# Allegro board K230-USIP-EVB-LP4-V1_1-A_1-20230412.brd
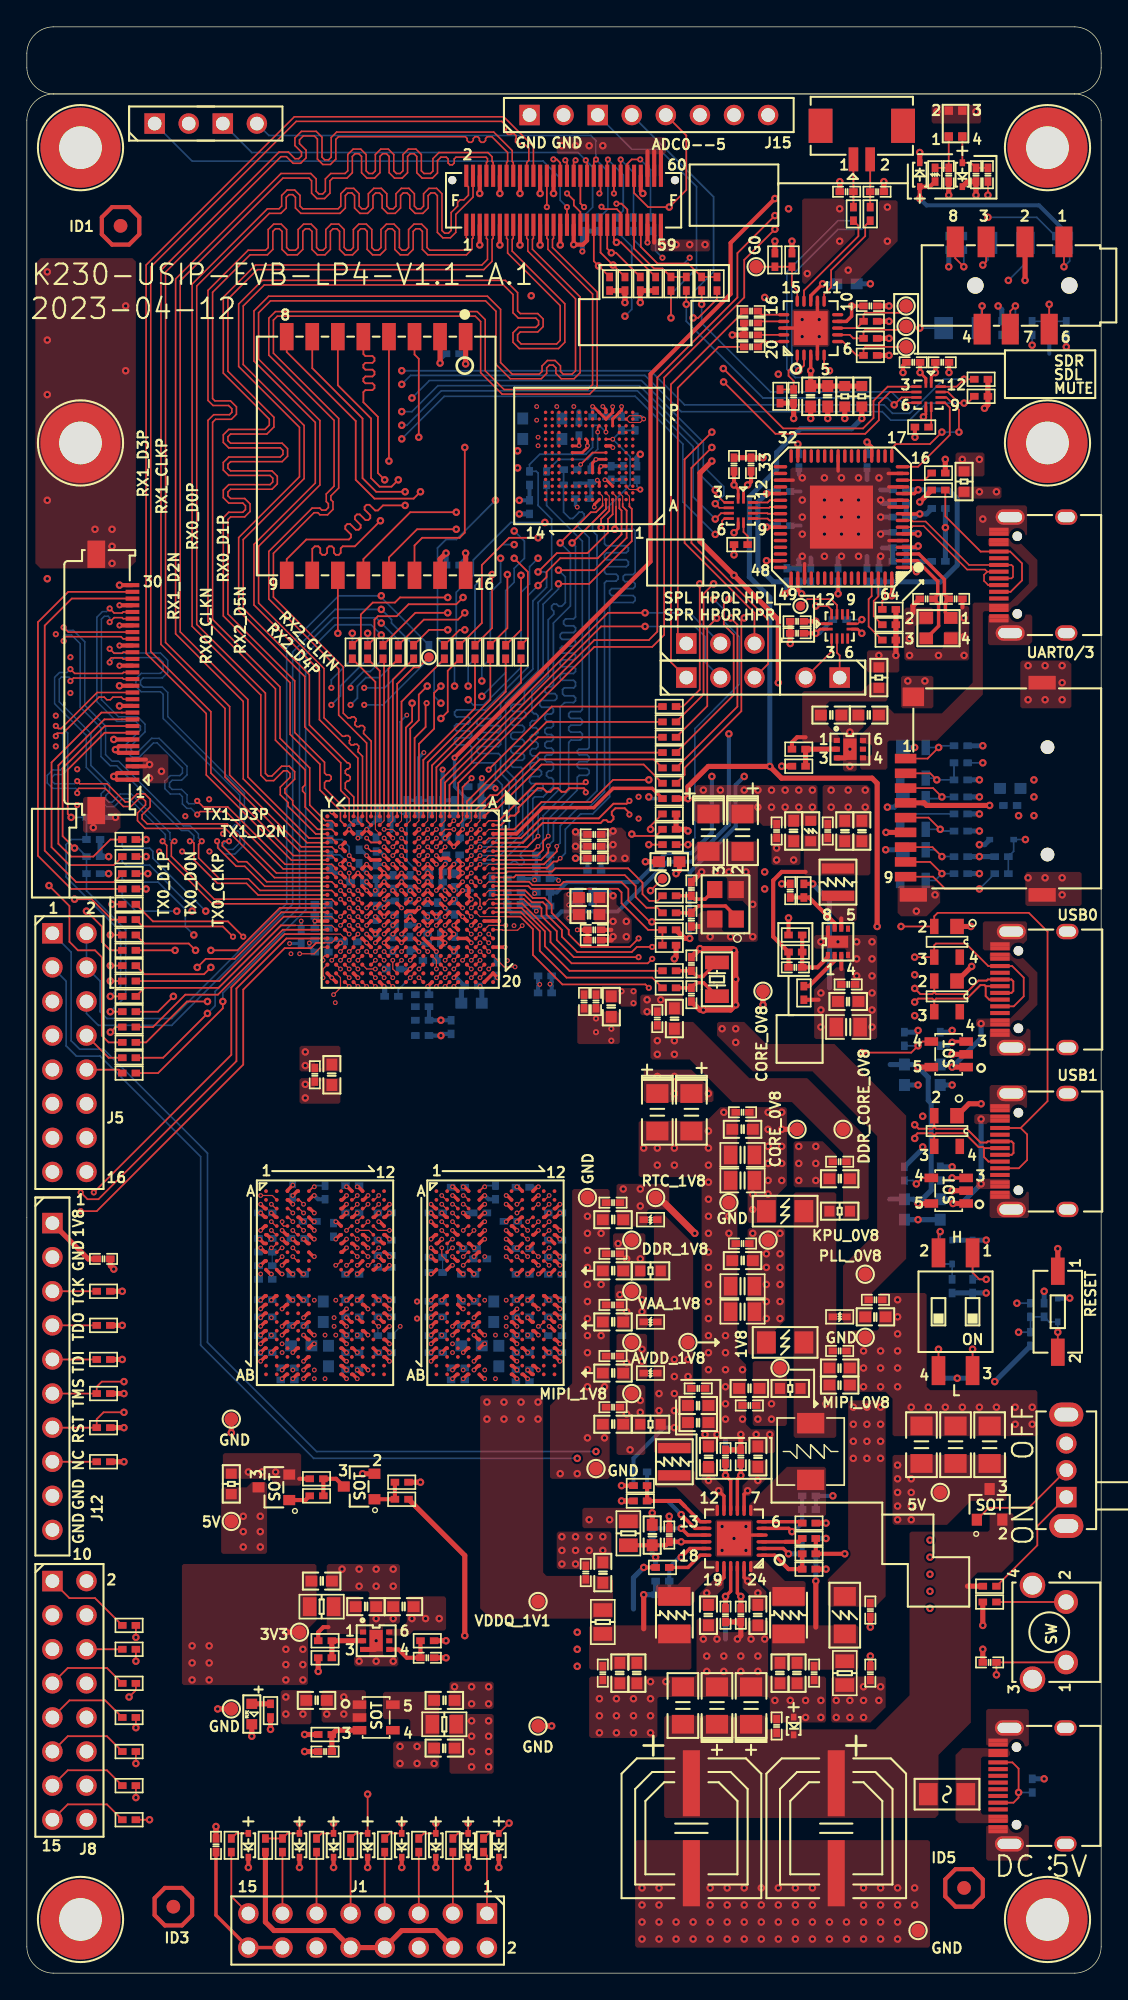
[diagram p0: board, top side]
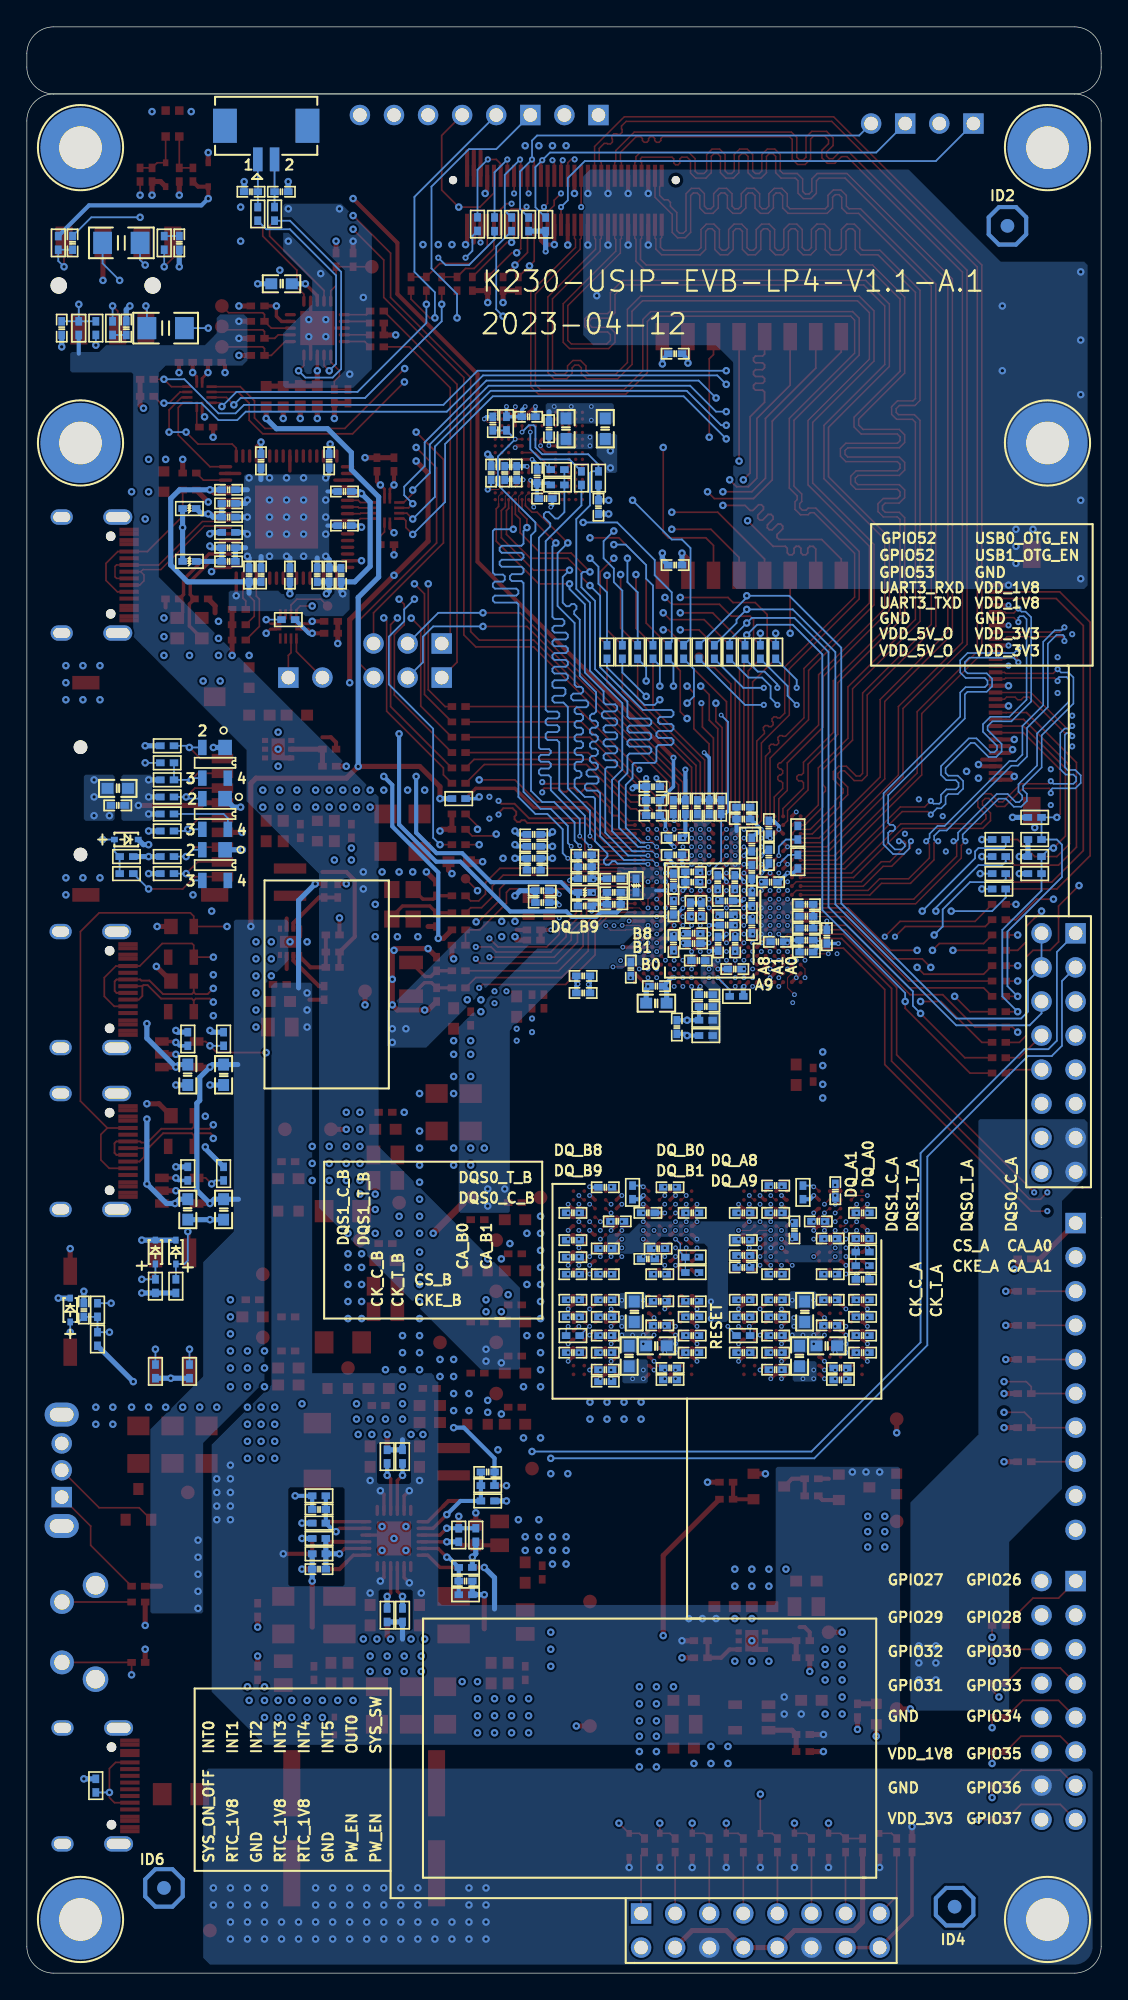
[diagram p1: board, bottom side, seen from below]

Outline 80.07 x 145 mm; copper layers: TOP, GND02, ART03, POWER04, GND05, ART06, GND07, BOTTOM. Coordinates in mm from the lower left corner of the outline.
Outline path: 2,140 arc(0.59,139.41) 0,138 0,2 arc(0.59,0.59) 2,0 78.07,0 arc(79.48,0.59) 80.07,2 80.07,138 arc(79.48,139.41) 78.07,140 ; 2,140 arc(0.59,140.59) 0,142 0,143 arc(0.59,144.41) 2,145 78.07,145 arc(79.48,144.41) 80.07,143 80.07,142 arc(79.48,140.59) 78.07,140 ; 2,140 78.07,140 ; 2,140 78.07,140

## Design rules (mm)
net group 3D_CTRL_IN: nets 3D_CTRL_IN N21013370
net group 3D_CTRL_OUT1: nets 3D_CTRL_OUT1 N21013374
net group 3D_CTRL_OUT2: nets 3D_CTRL_OUT2 N21013378
net group ADC_2: nets ADC_2 N21252475
net group ADC_3: nets ADC_3 N21252478
net group ADC_4: nets ADC_4 N21252481
net group DIFF100: nets DEBUG_DM DEBUG_DP
net group DL_M_CLK2: nets DL_M_CLK2 N21014154
net group DL_M_CLK3: nets DL_M_CLK3 N21014156
net group DP_M_CLK1: nets DP_M_CLK1 N21013382
net group EMMC_CLK: nets EMMC_CLK N21433380
net group EMMC_STROBE: nets EMMC_STROBE N21377535
net group GPIO26: nets GPIO26 N21015638
net group GPIO27: nets GPIO27 N21015640
net group GPIO28: nets GPIO28 N21015650
net group GPIO32: nets GPIO32 N21015658
net group GPIO33: nets GPIO33 N21015660
net group GPIO34: nets GPIO34 N21015662
net group GPIO35: nets GPIO35 N21015664
net group GPIO36: nets GPIO36 N21015666
net group GPIO37: nets GPIO37 N21015668
net group GPIO47: nets GPIO47 N21014397
net group GPIO48: nets GPIO48 N21014399
net group GPIO49: nets GPIO49 N21014401
net group GPIO52: nets GPIO52 N21015121
net group GPIO60_3V3: nets GPIO60_3V3 N21015137
net group GPIO61_3V3: nets GPIO61_3V3 N21015139
net group I2C1_SCL: nets I2C1_SCL N21014383
net group I2C1_SDA: nets I2C1_SDA N21014385
net group I2C3_SCL: nets I2C3_SCL N21014391
net group I2C3_SDA: nets I2C3_SDA N21014393
net group I2C4_SCL: nets I2C4_SCL N21013358
net group I2C4_SDA: nets I2C4_SDA N21013362
net group MMC1_CLK: nets MMC1_CLK N21015127
net group MMC1_CMD: nets MMC1_CMD N21015125
net group MMC1_D0: nets MMC1_D0 N21015129
net group MMC1_D1: nets MMC1_D1 N21015131
net group MMC1_D2: nets MMC1_D2 N21015133
net group MMC1_D3: nets MMC1_D3 N21015135
net group N21049039: nets N21049039 N21049045
net group N21049041: nets N21049041 N21049043
net group RESET_N_A_B: nets N21620702 RESET_N_A_B
net group RTC_CLK_IN: nets N20962782 RTC_CLK_IN
net group RTC_CLK_OUT: nets N20962780 RTC_CLK_OUT
net group RTC_INT0: nets N21140162 RTC_INT0
net group RTC_INT1: nets N21140164 RTC_INT1
net group RTC_INT2: nets N21140180 RTC_INT2
net group RTC_INT3: nets N21140182 RTC_INT3
net group RTC_INT4: nets N21259420 RTC_INT4
net group RTC_INT5: nets N21259407 RTC_INT5
net group RTC_OUT0: nets N21259441 RTC_OUT0
net group RTC_OUT1: nets RTC_OUT1 SYS_RST
net group SYS_CLK_IN: nets N20990724 SYS_CLK_IN
net group SYS_CLK_OUT: nets N20990759 SYS_CLK_OUT
net group SYS_SW: nets N21259446 SYS_SW
net group UART3_RXD: nets N21015111 UART3_RXD
net group UART3_TXD: nets N21015109 UART3_TXD
net group 18MIL: nets EMMC_RST JTAG_RST JTAG_TCK
net group ADC_0: nets ADC_0 HSY0 N21014379 N21252465 UART0_TXD
net group ADC_1: nets ADC_1 N21014381 N21252472 UART0_RXD VSY0
net group ADC_5: nets ADC_5 HP_INSERT_DET N21252484
net group BUS-DATA1-A: nets DQ_A13
net group DIFF90: nets USB0_DN USB0_DP USB1_DN USB1_DP
net group DP_RST: nets DP_RST GPIO46 N21014395
net group DP_STROBE: nets DP_STROBE GPIO42 N21014387
net group DP_VSYNC: nets DP_VSYNC GPIO43 N21014389
net group GPIO9: nets GPIO9 LCD_RST N21013366
net group GPIO29: nets GPIO29 N21015652 TOUCH_INT
net group GPIO30: nets GPIO30 N21015654 TOUCH_RST
net group GPIO31: nets GPIO31 LCD_EN N21015656
net group GPIO53: nets GPIO53 N21015123 N21453086

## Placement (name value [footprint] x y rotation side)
C1  100nF/16V  [C0402]  71.75 23.15 180 top
C2  22uF/16V-1206  [C1206]  71.75 39.37 90 top
C3  12pF/50V  [C0402]  49.53 72.9 270 top
C4  12pF/50V  [C0402]  49.53 75.18 90 top
C5  100nF/16V  [C0402]  31.88 76.71 270 bottom
C6  100nF/16V  [C0402]  35.05 74.8 270 bottom
C7  10uF/10V-0603  [C0603]  58.42 117.47 270 top
C8  12pF/50V  [C0402]  49.53 78.49 270 top
C9  22uF/16V-1206  [C1206]  48.9 19.94 90 top
C10  1nF/50V  [C0402]  63.36 132.72 0 bottom
C11  12pF/50V  [C0402]  49.53 80.77 90 top
C12  100nF/16V  [C0402]  55.88 18.41 90 top
C13  100nF/16V  [C0402]  75.82 49.4 270 bottom
C14  100nF/16V  [C0402]  31.75 83.31 180 bottom
C15  100nF/16V  [C0402]  42.29 83.06 0 bottom
C16  10uF/10V-0603  [C0603]  65.41 66.93 90 bottom
C17  10uF/10V-0603  [C0603]  68.07 66.93 270 bottom
C18  100nF/16V  [C0402]  41.15 115.06 90 bottom
C19  1uF/6.3V  [C0402]  44.45 111.76 270 bottom
C20  10uF/10V-0603  [C0603]  65.41 56.9 90 bottom
C21  10uF/10V-0603  [C0603]  68.07 56.9 270 bottom
C22  100nF/16V  [C0402]  43.56 111.76 270 bottom
C23  10uF/10V-0603  [C0603]  36.96 115.06 270 bottom
C24  100nF/16V  [C0402]  45.47 111.76 90 bottom
C25  100nF/16V  [C0402]  45.34 115.44 90 bottom
C26  100nF/16V  [C0402]  24.13 76.83 180 bottom
C27  100nF/16V  [C0402]  28.32 86.87 90 bottom
C28  100nF/16V  [C0402]  21.97 79.63 180 bottom
C29  100nF/16V  [C0402]  30.1 86.87 90 bottom
C30  100nF/16V  [C0402]  26.67 85.98 180 bottom
C31  100nF/16V  [C0402]  21.97 77.85 180 bottom
C32  100nF/16V  [C0402]  31.88 79.38 90 bottom
C33  10uF/10V-0603  [C0603]  41.91 80.14 0 top
C34  1uF/6.3V  [C0402]  42.29 76.96 0 top
C35  100nF/16V  [C0402]  38.48 81.53 180 bottom
C36  100nF/16V  [C0402]  38.61 73.03 0 bottom
C37  100nF/16V  [C0402]  38.61 74.3 0 bottom
C38  100nF/16V  [C0402]  28.57 81.28 270 bottom
C39  100nF/16V  [C0402]  27.3 81.28 270 bottom
C40  100nF/16V  [C0402]  27.94 79.88 180 bottom
C41  10uF/10V-0603  [C0603]  41.91 78.87 0 top
C42  1uF/6.3V  [C0402]  42.29 77.72 0 top
C43  100nF/16V  [C0402]  41.66 80.64 0 bottom
C44  100nF/16V  [C0402]  41.66 79.76 0 bottom
C45  100nF/16V  [C0402]  38.48 83.31 180 bottom
C46  100nF/16V  [C0402]  26.04 77.98 270 bottom
C47  100nF/16V  [C0402]  26.04 80.01 90 bottom
C48  100nF/16V  [C0402]  38.48 82.42 180 bottom
C49  10uF/10V-0603  [C0603]  47.88 82.8 0 top
C50  1uF/6.3V  [C0402]  42.29 83.95 0 top
C51  100nF/16V  [C0402]  42.29 84.84 0 top
C52  100nF/16V  [C0402]  30.48 81.28 0 bottom
C53  100nF/16V  [C0402]  42.29 83.95 0 bottom
C54  100nF/16V  [C0402]  42.29 84.84 0 bottom
C55  100nF/16V  [C0402]  42.29 83.06 0 top
C56  100nF/16V  [C0402]  30.48 82.04 0 bottom
C57  10uF/10V-0603  [C0603]  43.56 72.01 270 top
C58  1uF/6.3V  [C0402]  30.61 79.25 90 bottom
C59  100nF/16V  [C0402]  42.42 72.39 270 top
C60  100nF/16V  [C0402]  41.53 72.39 270 top
C61  100nF/16V  [C0402]  29.79 79.25 90 bottom
C62  100nF/16V  [C0402]  29.46 72.01 0 bottom
C63  10uF/10V-0603  [C0603]  48.26 71.12 90 top
C64  1uF/6.3V  [C0402]  46.99 71.12 90 top
C65  100nF/16V  [C0402]  21.97 76.96 0 bottom
C66  100nF/16V  [C0402]  21.97 76.07 0 bottom
C67  100nF/16V  [C0402]  27.91 78.84 180 bottom
C68  100nF/16V  [C0402]  27.91 78.08 0 bottom
C69  10uF/10V-0603  [C0603]  22.73 66.93 270 top
C70  1uF/6.3V  [C0402]  21.46 66.93 270 top
C71  100nF/16V  [C0402]  27.3 74.8 0 bottom
C72  100nF/16V  [C0402]  31.62 70.48 270 bottom
C73  100nF/16V  [C0402]  30.38 77.47 0 bottom
C74  100nF/16V  [C0402]  28.55 76.68 270 bottom
C75  100nF/16V  [C0402]  27.28 76.68 270 bottom
C76  1uF/6.3V  [C0402]  33.15 73.53 180 bottom
C77  100nF/16V  [C0402]  30.38 76.71 0 bottom
C78  1uF/6.3V  [C0402]  38.48 79.5 180 bottom
C79  100nF/16V  [C0402]  29.21 86.87 90 bottom
C80  100nF/16V  [C0402]  21.97 78.74 180 bottom
C81  1uF/6.3V  [C0402]  26.67 86.87 180 bottom
C82  100nF/16V  [C0402]  36.32 80.52 0 bottom
C83  1uF/6.3V  [C0402]  36.32 79.63 0 bottom
C84  100nF/16V  [C0402]  36.32 81.53 0 bottom
C85  1uF/6.3V  [C0402]  24.77 85.34 90 bottom
C86  100nF/16V  [C0402]  24.77 83.19 90 bottom
C87  100nF/16V  [C0402]  26.04 84.07 90 bottom
C88  1uF/6.3V  [C0402]  20.45 77.22 90 bottom
C89  100nF/16V  [C0402]  24.64 81.28 180 bottom
C90  100nF/16V  [C0402]  26.04 82.04 270 bottom
C91  10uF/10V-0603  [C0603]  22.48 45.97 270 bottom
C92  1uF/6.3V  [C0402]  26.67 50.16 180 bottom
C93  100nF/16V  [C0402]  24.26 56.64 0 bottom
C94  100nF/16V  [C0402]  26.67 46.23 180 bottom
C95  100nF/16V  [C0402]  26.67 56.64 180 bottom
C96  100nF/16V  [C0402]  26.67 53.47 180 bottom
C97  100nF/16V  [C0402]  19.81 58.29 90 bottom
C98  100nF/16V  [C0402]  24.26 47.5 0 bottom
C99  100nF/16V  [C0402]  24.26 50.16 180 bottom
C100  100nF/16V  [C0402]  24.26 52.07 180 bottom
C101  100nF/16V  [C0402]  21.08 56.01 180 bottom
C102  100nF/16V  [C0402]  26.67 52.58 180 bottom
C103  10uF/10V-0603  [C0603]  20.45 46.74 180 bottom
C104  1uF/6.3V  [C0402]  26.67 48.9 180 bottom
C105  100nF/16V  [C0402]  22.86 55.37 90 bottom
C106  100nF/16V  [C0402]  17.78 48.9 0 bottom
C107  100nF/16V  [C0402]  20.19 52.07 0 bottom
C108  100nF/16V  [C0402]  17.78 56.64 0 bottom
C109  100nF/16V  [C0402]  17.78 50.16 0 bottom
C110  100nF/16V  [C0402]  20.19 50.16 0 bottom
C111  100nF/16V  [C0402]  17.78 46.23 0 bottom
C112  100nF/16V  [C0402]  19.43 44.2 180 bottom
C113  100nF/16V  [C0402]  19.43 45.09 0 bottom
C114  100nF/16V  [C0402]  24.26 44.96 0 bottom
C115  10uF/10V-0603  [C0603]  22.1 49.28 90 bottom
C116  1uF/6.3V  [C0402]  17.78 47.5 0 bottom
C117  100nF/16V  [C0402]  26.67 54.61 180 bottom
C118  100nF/16V  [C0402]  20.19 54.74 0 bottom
C119  100nF/16V  [C0402]  17.78 54.74 180 bottom
C120  100nF/16V  [C0402]  24.26 48.9 0 bottom
C121  100nF/16V  [C0402]  20.19 48.26 0 bottom
C122  100nF/16V  [C0402]  24.26 46.23 0 bottom
C123  100nF/16V  [C0402]  24.26 58.67 0 bottom
C127  2.2uF/10V-0603  [C0603]  28.07 27.3 180 top
C128  22uF/6.3V-0603  [C0603]  25.27 27.3 180 top
C129  NC  [C0402]  29.84 23.5 0 top
C139  100nF/16V  [C0402]  73.29 87 0 bottom
C145  22uF/6.3V-0603  [C0603]  73.29 88.27 0 bottom
C149  4.7uF/6.3V  [C0402]  30.99 86.87 90 bottom
C150  100nF/16V  [C0402]  31.75 84.58 0 bottom
C151  4.7uF/6.3V  [C0402]  42.29 82.17 0 bottom
C152  4.7uF/6.3V  [C0402]  33.4 86.23 0 bottom
C153  100nF/16V  [C0402]  33.4 87.38 0 bottom
C154  100nF/16V  [C0402]  33.4 88.39 0 bottom
C155  100nF/16V  [C0402]  68.71 133.99 270 top
C156  100nF/16V  [C0402]  31.88 86.87 90 bottom
C157  100nF/16V  [C0402]  76.66 128.91 270 bottom
C158  100nF/16V  [C0402]  68.71 128.91 90 bottom
C159  22uF/16V-1206  [C1206]  69.72 122.56 0 bottom
C160  100nF/16V  [C0402]  72.66 122.56 270 bottom
C161  22uF/16V-1206  [C1206]  73.03 128.91 180 bottom
C162  100nF/16V  [C0402]  77.47 122.56 270 bottom
C199  4.7uF/6.3V  [C0402]  65.03 110.51 0 bottom
C200  100nF/16V  [C0402]  57.54 112.67 90 bottom
C201  12pF/50V  [C0402]  67.06 102.38 180 top
C202  100nF/16V  [C0402]  56.65 104.16 270 bottom
C203  4.7uF/6.3V  [C0402]  62.62 112.67 90 bottom
C204  12pF/50V  [C0402]  69.22 102.38 0 top
C205  100nF/16V  [C0402]  31.88 81.41 90 bottom
C206  100nF/16V  [C0402]  5.71 53.21 180 top
C207  100nF/16V  [C0402]  66.06 120.01 180 top
C208  100nF/16V  [C0402]  68.22 120.01 180 top
C216  100nF/16V  [C0402]  58.43 104.16 270 bottom
C217  100nF/16V  [C0402]  57.54 104.16 270 bottom
C218  100nF/16V  [C0402]  60.46 104.16 270 bottom
C219  100nF/16V  [C0402]  56.4 107.84 180 bottom
C220  100nF/16V  [C0402]  62.61 104.16 270 bottom
C221  100nF/16V  [C0402]  56.4 110.38 180 bottom
C222  100nF/16V  [C0402]  63.51 104.16 270 bottom
C223  4.7uF/6.3V  [C0402]  65.03 108.48 180 bottom
C224  100nF/16V  [C0402]  65.03 109.49 180 bottom
C225  4.7uF/6.3V  [C0402]  65.03 106.19 180 bottom
C226  100nF/16V  [C0402]  65.03 105.18 180 bottom
C227  22uF/6.3V-0603  [C0603]  21.97 29.21 180 top
C238  100nF/16V  [C0402]  71.63 133.99 90 top
C242  100nF/16V  [C0402]  31.75 120.65 0 bottom
C244  10uF/10V-0603  [C0603]  39.88 115.06 270 bottom
C247  330uF/25V  [C1010_8383_6666]  49.53 10.79 180 top
C248  330uF/25V  [C1010_8383_6666]  60.33 10.79 180 top
C249  10uF/16V-1206  [TC1206]  51.44 19.94 90 top
C250  10uF/16V-1206  [TC1206]  53.98 19.94 90 top
C251  10uF/16V-1206  [TC1206]  49.53 64.14 270 top
C252  10uF/16V-1206  [TC1206]  53.34 84.96 270 top
C253  10uF/16V-1206  [TC1206]  46.99 64.14 270 top
C254  10uF/16V-1206  [TC1206]  50.8 84.96 270 top
C256  1uF/6.3V  [C0402]  41.4 109.86 180 bottom
C257  100nF/16V  [C0402]  42.67 115.95 180 bottom
C258  100nF/16V  [C0402]  42.04 111.51 90 bottom
C259  100nF/16V  [C0402]  37.47 109.22 270 bottom
C260  100nF/16V  [C0402]  31.75 104.9 180 bottom
C261  100nF/16V  [C0402]  29.46 72.9 180 bottom
C262  1nF/50V  [C0402]  30.02 75.44 0 bottom
C263  100nF/16V  [C0402]  17.78 51.69 180 bottom
C264  10uF/10V-0603  [C0603]  35.18 45.97 270 bottom
C265  1uF/6.3V  [C0402]  30.48 56.64 0 bottom
C266  100nF/16V  [C0402]  39.37 56.64 180 bottom
C268  NC  [C0402]  14.1 9.53 90 top
C269  10uF/10V-0603  [C0603]  33.15 72.26 180 bottom
C272  100nF/16V  [C0402]  32.13 58.55 180 bottom
C273  100nF/16V  [C0402]  36.96 50.16 180 bottom
C274  100nF/16V  [C0402]  39.37 46.23 180 bottom
C275  100nF/16V  [C0402]  30.48 46.23 0 bottom
C276  100nF/16V  [C0402]  36.96 52.07 180 bottom
C277  100nF/16V  [C0402]  36.96 47.5 0 bottom
C278  10uF/10V-0603  [C0603]  33.15 46.74 180 bottom
C279  1uF/6.3V  [C0402]  36.96 44.07 180 bottom
C280  100nF/16V  [C0402]  39.37 50.16 180 bottom
C281  100nF/16V  [C0402]  30.48 50.05 0 bottom
C282  100nF/16V  [C0402]  39.37 48.9 180 bottom
C283  100nF/16V  [C0402]  36.96 46.23 0 bottom
C284  100nF/16V  [C0402]  39.37 53.34 180 bottom
C285  100nF/16V  [C0402]  39.37 52.07 0 bottom
C286  100nF/16V  [C0402]  36.96 58.55 0 bottom
C287  100nF/16V  [C0402]  30.48 48.9 0 bottom
C288  100nF/16V  [C0402]  32.89 50.05 0 bottom
C289  100nF/16V  [C0402]  36.96 44.96 0 bottom
C290  100nF/16V  [C0402]  32.13 44.2 180 bottom
C291  100nF/16V  [C0402]  32.13 45.09 0 bottom
C292  100nF/16V  [C0402]  36.07 56.01 0 bottom
C293  100nF/16V  [C0402]  33.78 56.64 180 bottom
C294  100nF/16V  [C0402]  32.89 52.07 0 bottom
C295  100nF/16V  [C0402]  33.78 53.21 0 bottom
C296  10uF/10V-0603  [C0603]  34.8 49.28 90 bottom
C297  1uF/6.3V  [C0402]  36.96 48.9 0 bottom
C298  100nF/16V  [C0402]  39.37 54.61 180 bottom
C299  100nF/16V  [C0402]  33.02 53.98 180 bottom
C300  100nF/16V  [C0402]  36.96 53.99 0 bottom
C301  100nF/16V  [C0402]  32.89 48.26 0 bottom
C302  100nF/16V  [C0402]  30.48 47.5 0 bottom
C303  10uF/10V-0603  [C0603]  59.69 117.47 270 top
C304  10uF/10V-0603  [C0603]  61.09 125.86 0 bottom
C305  1nF/50V  [C0402]  61.1 132.72 180 bottom
C306  1nF/50V  [C0402]  61.1 132.72 180 top
C307  1nF/50V  [C0402]  63.36 132.72 0 top
C308  100nF/16V  [C0402]  62.87 124.21 0 top
C309  100nF/16V  [C0402]  53.98 121.16 0 top
C310  100nF/16V  [C0402]  53.98 122.05 0 top
C311  100nF/16V  [C0402]  53.98 123.83 0 top
C312  100nF/16V  [C0402]  53.98 122.94 0 top
C313  1uF/6.3V  [C0402]  57.15 117.47 270 top
C314  27pF/50V  [C0402]  70.74 133.99 270 top
C315  100nF/16V  [C0402]  57.4 99.82 180 top
C316  100nF/16V  [C0402]  57.4 100.71 0 top
C317  22uF/6.3V-0603  [C0603]  60.58 43.81 0 top
C318  100nF/16V  [C0402]  60.58 46.35 0 top
C319  22uF/6.3V-0603  [C0603]  60.58 45.09 0 top
C320  22pF/50V  [C0402]  58.29 34.54 180 bottom
C321  22uF/6.3V-0603  [C0603]  50.04 41.02 0 top
C322  22uF/6.3V-0603  [C0603]  50.04 42.29 0 top
C323  22pF/50V  [C0402]  45.72 37.34 0 bottom
C324  100nF/16V  [C0402]  50.04 43.56 0 top
C325  22uF/6.3V-0603  [C0603]  45.47 22.35 270 top
C326  100nF/16V  [C0402]  42.93 22.35 270 top
C327  22uF/6.3V-0603  [C0603]  44.2 22.35 270 top
C328  22pF/50V  [C0402]  47.37 29.21 0 bottom
C329  22uF/6.3V-0603  [C0603]  57.4 22.35 270 top
C330  100nF/16V  [C0402]  58.67 22.35 270 top
C331  22uF/6.3V-0603  [C0603]  56.13 22.35 270 top
C332  22pF/50V  [C0402]  58.29 30.1 180 bottom
C333  100nF/16V  [C0402]  52.07 38.48 90 top
C334  NC  [C0402]  53.21 38.48 90 top
C335  100nF/16V  [C0402]  53.21 26.67 270 top
C336  100nF/16V  [C0402]  52.07 26.67 270 top
C337  2.2uF/16V-0603  [C0603]  54.48 38.48 90 top
C338  2.2uF/16V-0603  [C0603]  50.8 26.67 270 top
C339  2.2uF/16V-0603  [C0603]  50.8 38.48 90 top
C340  2.2uF/16V-0603  [C0603]  54.48 26.67 270 top
C341  10uF/10V-0603  [C0603]  43.69 52.32 180 top
C342  100nF/16V  [C0402]  43.69 53.59 180 top
C343  10uF/10V-0603  [C0603]  43.69 56.13 180 top
C344  100nF/16V  [C0402]  43.69 57.4 180 top
C345  10uF/10V-0603  [C0603]  43.69 40.89 180 top
C346  100nF/16V  [C0402]  43.69 42.16 180 top
C347  10uF/10V-0603  [C0603]  42.93 29.84 90 top
C348  100nF/16V  [C0402]  41.66 29.84 90 top
C349  100nF/16V  [C0402]  47.88 32.64 90 top
C350  10uF/10V-0603  [C0603]  46.61 32.64 90 top
C351  100nF/16V  [C0402]  53.34 64.14 180 top
C352  10uF/10V-0603  [C0603]  53.34 62.87 180 top
C353  100nF/16V  [C0402]  53.34 54.36 180 top
C354  10uF/10V-0603  [C0603]  53.34 53.09 180 top
C357  100nF/16V  [C0402]  53.85 42.29 180 top
C358  10uF/10V-0603  [C0603]  53.85 43.56 180 top
C359  100nF/16V  [C0402]  43.69 49.78 180 top
C360  10uF/10V-0603  [C0603]  43.69 48.51 180 top
C361  100nF/16V  [C0402]  43.69 45.97 180 top
C362  10uF/10V-0603  [C0603]  43.69 44.7 180 top
C365  100nF/16V  [C0402]  63.25 50.16 0 top
C366  10uF/10V-0603  [C0603]  63.25 48.9 0 top
C367  100nF/16V  [C0402]  52.7 112.39 270 top
C368  100nF/16V  [C0402]  53.98 112.39 90 top
C369  22uF/6.3V-0603  [C0603]  59.94 93.73 180 top
C370  2.2uF/10V-0603  [C0603]  62.74 93.73 180 top
C371  47uF/6.3V-0805  [C0805]  53.34 60.96 180 top
C372  47uF/6.3V-0805  [C0805]  53.34 59.05 180 top
C373  47uF/6.3V-0805  [C0805]  53.34 49.28 180 top
C374  47uF/6.3V-0805  [C0805]  53.34 51.18 180 top
C375  10uF/10V-0603  [C0603]  57.15 85.09 270 top
C376  100nF/16V  [C0402]  55.88 85.09 270 top
C377  100nF/16V  [C0402]  59.69 85.09 270 top
C378  22uF/6.3V-0603  [C0603]  60.96 85.09 90 top
C379  10uF/10V-0603  [C0603]  61.21 72.39 0 top
C380  22uF/6.3V-0603  [C0603]  62.23 85.09 90 top
C381  100nF/16V  [C0402]  61.21 73.66 180 top
C382  22pF/50V  [C0402]  57.28 74.93 180 top
C383  22uF/16V-0805  [C0805]  61.21 70.48 0 top
C394  NC  [C0402]  56.9 80.64 90 top
C395  10uF/10V-0603  [C0603]  60.58 59.18 180 top
C396  100nF/16V  [C0402]  60.58 60.45 180 top
C397  22uF/16V-1206  [C1206]  66.67 39.37 90 top
C398  22uF/16V-1206  [C1206]  69.22 39.37 90 top
C399  100nF/16V  [C0402]  62.87 22.35 90 top
C400  100nF/16V  [C0402]  62.87 27.05 270 top
C401  2.2uF/10V-0603  [C0603]  21.59 20.32 180 top
C402  NC  [C0402]  22.23 16.51 180 top
C403  22uF/6.3V-0603  [C0603]  31.11 16.76 0 top
C404  22uF/6.3V-0603  [C0603]  31.11 20.32 180 top
D1  NC  [SOD523-2-28-H]  57.15 18.41 270 top
F1  3A-12V  [F1206]  68.58 13.34 180 top
FB1  600R/100MHz-500mA  [FB0402]  67.69 133.99 90 top
FB4  600R/100MHz-500mA  [FB0402]  34.67 81.03 270 bottom
FB5  600R/100MHz-500mA  [FB0402]  38.48 80.52 0 bottom
FB7  600R/100MHz-500mA  [FB0402]  67.95 105.18 180 bottom
FB8  600R/100MHz-500mA  [FB0402]  67.95 109.11 180 bottom
FB19  600R/100MHz-500mA  [FB0402]  46.48 56.13 180 top
FB26  600R/100MHz-500mA  [FB0402]  46.48 48.51 180 top
FB27  600R/100MHz-500mA  [FB0402]  46.48 44.7 180 top
FB29  600R/100MHz-500mA  [FB0402]  60.58 48.9 0 top
FB31  30R/4A  [FB1206]  56.52 56.77 180 top
FB32  30R/4A  [FB1206]  56.52 46.99 180 top
FB34  NC  [FB0603]  58.42 85.09 90 top
FB38  NC  [FB1206]  60.96 26.67 90 top
GPIO1  TEST POINT SMD circle 35 mils  [TP28]  57.66 101.85 0 top
GPIO25  TEST POINT SMD circle 35 mils  [TP28]  29.97 98.04 0 top
ID1  -  [unnamed]  6.99 130.18 0 top
ID2  -  [unnamed]  6.99 130.18 180 bottom
ID3  -  [unnamed]  10.92 4.95 0 top
ID4  -  [unnamed]  10.92 4.95 180 bottom
ID5  -  [unnamed]  69.85 6.35 0 top
ID6  -  [unnamed]  69.85 6.35 180 bottom
J1  2X8_2.54mm  [HEAD2X8-100]  34.29 4.45 180 top
J2  TYPE-C  [TYPE-C-USB16-20-126-H-SMD-B]  76.36 13.95 90 top
J3  TH243-G60S-W0R01  [BTB2X30-050-F-SMD]  40.01 132.08 0 top
J4  FPC-05F-30PH20  [FPC30-005-0520-75]  7.87 96.16 270 top
J5  2X8_2.54mm  [HEAD2X8-100]  1.91 77.47 270 top
J6  TYPE-C  [TYPE-C-USB16-20-126-H-SMD-B]  76.42 104.16 90 top
J7  PJ35367  [AUDIO-PJ3536-7-197]  74.3 125.73 270 top
J8  2X8_2.54mm  [HEAD2X8-100]  1.91 29.21 270 top
J9  Flash-EXT  [SOP16-75]  26.04 113.03 270 top
J11  TYPE-C  [TYPE-C-USB16-20-126-H-SMD-B]  76.5 73.28 90 top
J12  10pin 2.54mm  [HEAD10-100]  1.91 48.26 270 top
J13  TYPE-C  [TYPE-C-USB16-20-126-H-SMD-B]  76.5 61.21 90 top
J14  NC  [HEAD2-100]  37.47 138.43 0 top
J15  NC  [HEAD6-100]  42.55 138.43 0 top
J16  NC  [HEAD2-100]  14.61 137.79 0 top
J17  NC  [HEAD2-100]  9.53 137.79 0 top
J18  2P-SMD-1.25  [CON2-075053-036]  62.23 137.79 180 bottom
J19  2P-SMD-1.25  [CON2-075053-036]  62.23 137.79 0 top
J20  3_ 2.54mm  [HEAD3-100]  49.15 99.06 0 top
J21  3_ 2.54mm  [HEAD3-100]  49.15 96.52 0 top
J22  NC  [HEAD2-100]  60.58 96.52 180 top
K1  KH-6X6X8H-ZJ  [DSW4-KH-6X6X7H-ZJ]  76.2 25.4 90 top
K2  TS-KG07U  [SW2-061036-025]  76.83 49.28 90 top
K4  SK12D07VG3  [DSW3-087044-047-H]  77.47 37.47 90 top
L4  2.2uH/2.6A  [PL02_502-01]  60.45 81.28 90 top
L5  2.2uH/4.6A  [PL0505-030]  58.42 38.86 90 top
L7  1.5uH/2.7A  [PL0303-017A]  48.26 26.67 270 top
L11  2.2uH/2.6A  [PL02_502-01]  48.26 38.1 90 top
L12  1.5uH/2.7A  [PL0303-017A]  56.77 26.67 270 top
LED1  RED 0603  [LED0603]  16.76 19.3 270 top
M1  M3  [HOLE-M3]  76.07 4 90 top
M2  M3  [HOLE-M3]  76.07 114 90 top
M3  M3  [HOLE-M3]  4 4 90 top
M4  M3  [HOLE-M3]  76.07 136 90 top
M5  M3  [HOLE-M3]  4 136 90 top
M6  M3  [HOLE-M3]  4 114 90 top
NOREF  -  [#2]  164.47 96.52 0 top
Q1  YJL2301C  [SOT23-3-43]  18.41 36.2 90 top
Q2  2N7002  [SOT23-3-43]  24.77 36.26 90 top
Q5  YJL3407AL  [SOT23-3-43]  71.75 34.92 0 top
R1  0R  [R0402]  34.04 9.53 270 top
R2  0R  [R0402]  31.75 9.53 270 top
R3  0R  [R0402]  29.21 9.53 270 top
R4  0R  [R0402]  26.67 9.53 270 top
R5  0R  [R0402]  47.88 73.41 0 top
R6  0R  [R0402]  47.88 74.68 180 top
R7  NC  [R0402]  4.95 86.11 0 bottom
R8  0R  [R0402]  47.88 78.99 180 top
R9  5.1K/1%  [R0402]  74.93 13.97 90 bottom
R10  0R  [R0402]  47.88 80.26 180 top
R11  0R-0603  [R0603]  60.96 117.47 270 top
R12  0R  [R0402]  24.13 9.53 270 top
R13  0R  [R0402]  70.48 44.83 270 bottom
R14  0R  [R0402]  67.94 44.83 270 bottom
R15  0R  [R0402]  21.59 9.53 270 top
R16  0R  [R0402]  19.05 9.53 270 top
R17  0R  [R0402]  15.24 9.53 270 top
R18  10K  [R0402]  70.48 51.18 270 bottom
R19  200R/1%  [R0402]  18.16 19.56 90 top
R20  10K  [R0402]  68.96 51.18 270 bottom
R22  NC  [R0402]  74.8 49.4 270 bottom
R23  5.1K/1%  [R0402]  21.59 36.83 180 top
R25  0R  [R0402]  47.88 89.79 180 top
R26  0R  [R0402]  47.88 92.08 180 top
R27  0R  [R0402]  47.88 88.65 180 top
R28  0R  [R0402]  47.88 94.36 180 top
R29  0R  [R0402]  47.88 90.93 180 top
R30  0R  [R0402]  47.88 93.22 180 top
R31  2K/1%  [R0402]  77.72 128.91 270 bottom
R33  0R  [R0402]  69.83 128.91 270 bottom
R34  0R  [R0402]  73.68 122.56 90 bottom
R35  10K  [R0402]  76.2 122.56 90 bottom
R39  30K/1%  [R0402]  47.88 87.5 0 bottom
R40  10K  [R0402]  68.07 69.6 270 bottom
R41  10K  [R0402]  65.41 69.6 90 bottom
R42  200R/1%  [R0402]  47.88 86.36 0 top
R43  30K/1%  [R0402]  47.88 87.5 0 top
R44  200R/1%  [R0402]  47.88 85.22 0 top
R45  10K  [R0402]  68.07 59.56 270 bottom
R46  10K  [R0402]  65.41 59.56 90 bottom
R47  0R  [R0402]  40.51 112.01 0 bottom
R48  10K  [R0402]  37.47 111.38 270 bottom
R49  10K  [R0402]  44.32 115.44 90 bottom
R50  0R  [R0402]  38.73 111.38 90 bottom
R51  0R  [R0402]  48.01 125.86 90 top
R52  0R  [R0402]  51.44 125.86 90 top
R53  NC  [R0402]  49.15 125.86 270 top
R54  NC  [R0402]  50.29 125.86 270 top
R55  0R  [R0402]  72.64 81.92 0 bottom
R56  200R/1%  [R0402]  22.61 82.8 90 bottom
R57  1K/1%  [R0402]  29.46 70.99 180 bottom
R58  1K/1%  [R0402]  29.46 69.85 0 bottom
R59  NC  [R0402]  40.51 110.87 0 bottom
R61  240R/1%  [R0402]  27.18 72.77 180 bottom
R62  10K  [R0402]  17.78 9.53 270 top
R63  0R  [R0402]  17.78 53.72 180 bottom
R64  0R  [R0402]  26.67 47.5 0 bottom
R65  NC  [R0402]  22.61 84.96 270 bottom
R66  240R/1%  [R0402]  22.23 58.17 270 bottom
R67  0R  [R0402]  30.48 52.2 180 bottom
R68  0R  [R0402]  39.37 47.5 0 bottom
R69  240R/1%  [R0402]  34.92 58.17 270 bottom
R72  NC  [R0402]  17.78 52.7 180 bottom
R73  NC  [R0402]  30.48 53.34 180 bottom
R74  NC  [R0402]  4.95 81.92 0 bottom
R75  NC  [R0603]  15.24 36.45 270 top
R76  0R  [R0402]  27.94 35.31 180 top
R77  0R  [R0402]  7.62 72.77 0 top
R78  0R  [R0402]  21.59 35.56 180 top
R79  0R  [R0402]  7.62 71.63 0 top
R80  10K  [R0402]  62.87 121.79 180 top
R81  0R  [R0402]  7.62 81.92 180 bottom
R82  0R  [R0402]  62.86 131.06 90 bottom
R83  0R  [R0402]  7.62 77.34 0 top
R84  0R  [R0402]  61.61 131.06 90 bottom
R85  0R  [R0402]  7.62 70.48 0 top
R86  0R  [R0402]  61.61 131.06 90 top
R87  0R  [R0402]  7.62 78.49 0 top
R88  NC  [R0603]  62.23 117.47 270 top
R89  0R  [R0402]  7.62 76.2 0 top
R90  0R  [R0402]  62.86 131.06 90 top
R91  0R  [R0402]  7.62 25.91 0 top
R92  0R  [R0402]  32.26 98.42 90 top
R93  0R  [R0402]  7.62 73.91 0 top
R94  0R  [R0402]  32.26 98.42 90 bottom
R95  0R  [R0402]  7.62 75.06 0 top
R96  0R  [R0402]  34.54 98.42 90 top
R97  0R  [R0402]  7.62 84.45 180 bottom
R98  0R  [R0402]  33.4 98.42 90 top
R99  0R  [R0402]  7.62 83.19 180 bottom
R100  0R  [R0402]  35.69 98.42 90 top
R101  0R  [R0402]  7.62 80.77 180 bottom
R102  0R  [R0402]  47.88 84.07 0 top
R103  0R  [R0402]  7.62 24.13 0 top
R104  0R  [R0402]  36.83 98.42 90 top
R105  0R  [R0402]  7.62 21.59 0 top
R106  0R  [R0402]  34.54 98.42 90 bottom
R107  0R  [R0402]  7.62 19.05 0 top
R108  0R  [R0402]  36.83 98.42 90 bottom
R109  0R  [R0402]  7.62 16.51 0 top
R110  0R  [R0402]  31.11 98.42 90 bottom
R111  0R  [R0402]  7.62 13.97 0 top
R112  0R  [R0402]  33.4 98.42 90 bottom
R113  0R  [R0402]  7.62 11.43 0 top
R114  0R  [R0402]  35.69 98.42 90 bottom
R115  0R  [R0402]  26.54 98.42 270 bottom
R116  0R  [R0402]  7.62 79.63 180 top
R117  0R  [R0402]  27.69 98.42 270 bottom
R118  0R  [R0402]  7.62 69.34 180 top
R119  0R  [R0402]  29.97 98.42 270 bottom
R120  0R  [R0402]  28.83 98.42 270 bottom
R121  0R  [R0402]  31.11 98.42 270 top
R122  0R  [R0402]  28.83 98.42 270 top
R123  0R  [R0402]  24.26 98.42 270 top
R124  0R  [R0402]  27.69 98.42 270 top
R125  0R  [R0402]  25.4 98.42 270 top
R126  0R  [R0402]  26.54 98.42 270 top
R127  0R  [R0402]  24.26 98.42 270 bottom
R128  0R  [R0402]  25.4 98.42 270 bottom
R129  NC  [R0402]  47.88 77.72 180 top
R130  NC  [R0402]  62.87 120.52 180 top
R131  10K  [R0402]  57.02 127.64 90 top
R132  10K  [R0402]  62.87 123.06 180 top
R133  NC  [R0402]  55.75 127.64 90 top
R134  1M  [R0402]  56.13 117.47 270 top
R137  200K/1%  [R0402]  27.94 36.58 180 top
R141  0R  [R0402]  7.62 68.2 0 top
R143  10K  [R0402]  29.84 24.77 180 top
R144  0R  [R0402]  7.62 67.06 0 top
R146  4.7K  [R0402]  60.58 100.84 0 bottom
R147  NC  [R0402]  69.61 90.17 180 bottom
R162  10K  [R0402]  69.61 87.63 180 bottom
R177  100K/1%  [R0402]  22.23 24.77 0 top
R178  20K/1%  [R0402]  22.23 23.5 180 top
R179  0R  [R0402]  43.94 130.29 270 bottom
R180  0R  [R0402]  45.21 130.29 270 bottom
R181  0R  [R0402]  46.48 130.3 270 bottom
R182  0R  [R0402]  7.62 84.45 0 top
R183  0R  [R0402]  7.62 83.19 0 top
R184  0R  [R0402]  7.62 81.92 0 top
R188  10K  [R0402]  69.61 85.09 180 bottom
R189  10K  [R0402]  69.61 83.19 180 bottom
R190  10K  [R0402]  69.61 81.92 180 bottom
R191  10K  [R0402]  69.61 91.44 180 bottom
R193  10K  [R0402]  69.61 88.9 180 bottom
R194  10K  [R0402]  72.64 83.19 0 bottom
R195  5.1K/1%  [R0402]  67.94 110.49 180 top
R197  10K  [R0402]  5.71 50.8 180 top
R198  NC  [R0402]  5.71 48.26 180 top
R199  10K  [R0402]  5.71 45.72 180 top
R200  10K  [R0402]  5.71 43.18 180 top
R201  10K  [R0402]  67.94 111.76 180 top
R202  12K/1%  [R0402]  65.03 107.34 0 bottom
R203  10K  [R0402]  64.26 101.6 180 top
R204  10K  [R0402]  64.26 100.46 180 top
R205  10K  [R0402]  64.26 99.31 180 top
R206  10K  [R0402]  5.71 40.64 180 top
R207  10K  [R0402]  5.71 38.1 180 top
R208  0R  [R0402]  7.62 80.77 0 top
R209  4.7K  [R0402]  66.7 115.18 0 top
R221  0R  [R0402]  74.93 122.56 90 bottom
R223  10K  [R0402]  74.8 47.24 270 bottom
R234  4.7K  [R0402]  41.4 130.29 90 bottom
R235  4.7K  [R0402]  42.67 130.29 90 bottom
R236  4.7K  [R0402]  4.95 84.45 180 bottom
R237  4.7K  [R0402]  4.95 83.19 180 bottom
R238  4.7K  [R0402]  43.43 125.86 90 top
R239  4.7K  [R0402]  44.58 125.86 90 top
R240  4.7K  [R0402]  45.72 125.86 90 top
R241  4.7K  [R0402]  46.86 125.86 90 top
R242  4.7K  [R0402]  71.12 118.75 180 top
R243  4.7K  [R0402]  71.12 117.47 180 top
R245  0R  [R0402]  69.61 86.36 0 bottom
R252  10K  [R0402]  47.88 76.58 180 top
R262  10K  [R0402]  71.75 27.65 180 top
R265  10K  [R0402]  52.07 38.48 90 bottom
R266  30K/1%  [R0402]  58.29 33.53 180 bottom
R267  10K/1%  [R0402]  58.29 35.56 0 bottom
R268  15K/1%  [R0402]  45.72 35.18 0 bottom
R269  30K/1%  [R0402]  45.72 36.32 180 bottom
R270  450K/1%  [R0402]  58.29 31.24 180 bottom
R271  100K/1%  [R0402]  58.29 32.38 0 bottom
R272  10K  [R0402]  53.21 38.48 90 bottom
R273  10K  [R0402]  53.21 26.67 270 bottom
R274  10K  [R0402]  52.07 26.67 270 bottom
R275  13.7K/1%  [R0402]  47.37 28.19 0 bottom
R276  16.5K/1%  [R0402]  47.37 30.23 0 bottom
R277  NC  [R0402]  58.29 32.38 180 top
R278  NC  [R0402]  58.29 33.53 180 top
R279  0R  [R0402]  45.72 35.18 180 top
R280  NC  [R0402]  45.72 36.32 180 top
R281  NC  [R0402]  47.88 32.64 90 bottom
R282  NC  [R0402]  46.61 32.64 90 bottom
R283  NC  [R0805]  44.83 32.77 90 top
R284  4.7K  [R0402]  53.21 106.43 180 top
R285  100K/1%  [R0402]  57.53 91.19 180 top
R286  20K/1%  [R0402]  57.53 89.92 180 top
R287  0R-0603  [R0603]  63.5 96.52 90 top
R288  NC  [R0603]  69.85 111.12 90 top
R289  NC  [R0402]  58.29 31.24 0 top
R290  0R  [R0402]  58.29 30.1 0 top
R293  10K  [R0402]  57.91 73.03 90 top
R294  10K/1%  [R0402]  57.28 76.07 180 top
R296  30K/1%  [R0402]  57.28 77.34 180 top
R301  10K  [R0402]  57.91 80.64 90 top
R302  NC  [R0402]  47.37 30.23 0 top
R303  1K  [R0402]  71.75 28.83 0 top
R304  10K  [R0402]  22.23 17.78 0 top
R305  0R-0805  [R0805]  31.11 18.54 0 top
R306  NC  [R0805]  21.97 27.3 180 top
R307  0R-0805  [R0805]  42.93 26.16 90 top
R308  0R-0805  [R0805]  60.96 22.35 270 top
R309  0R-0603  [R0603]  60.58 56.77 0 top
R310  0R-0603  [R0603]  56.9 43.56 180 top
R311  0R-0603  [R0603]  46.48 40.89 180 top
R312  0R-0603  [R0603]  46.48 52.32 180 top
SW1  KF1027B-02P-G00-ON-01B  [SW4-100-060050-035]  69.22 49.28 180 top
TP1  DI  [TP40]  45.09 54.61 0 top
TP2  DI  [TP40]  45.09 50.8 0 top
TP3  DI  [TP40]  60.83 62.87 0 top
TP4  DI  [TP40]  38.1 27.69 0 top
TP5  DI  [TP40]  54.86 73.15 0 top
TP6  DI  [TP40]  57.4 62.87 0 top
TP7  DI  [TP40]  62.48 52.07 0 top
TP8  DI  [TP40]  55.24 54.61 0 top
TP9  DI  [TP40]  49.28 46.99 0 top
TP10  DI  [TP40]  20.32 25.4 0 top
TP11  DI  [TP40]  45.09 46.99 0 top
TP12  DI  [TP40]  45.09 43.18 0 top
TP13  DI  [TP40]  46.86 57.78 0 top
TP14  DI  [TP40]  56.13 45.09 0 top
TP15  DI  [TP40]  66.42 3.17 0 top
TP16  DI  [TP40]  15.24 19.68 0 top
TP17  DI  [TP40]  15.24 41.27 0 top
TP18  DI  [TP40]  42.42 37.59 0 top
TP19  DI  [TP40]  38.1 18.41 0 top
TP20  DI  [TP40]  62.48 47.37 0 top
TP21  DI  [TP40]  41.78 57.78 0 top
TP22  DI  [TP40]  52.32 57.4 0 top
TP23  DI  [TP40]  68.07 35.81 0 top
TP24  DI  [TP40]  15.24 33.66 0 top
TP25  DI  [TP40]  65.53 121.16 0 top
TP26  DI  [TP40]  65.53 122.68 0 top
TP27  DI  [TP40]  65.53 124.21 0 top
TP28  DI  [TP40]  54.36 127.13 0 top
TVS1  ESD5B5.0ST1G  [SOD523-2-28]  35.18 9.53 270 top
TVS2  ESD5B5.0ST1G  [SOD523-2-28]  32.89 9.53 270 top
TVS3  ESD5B5.0ST1G  [SOD523-2-28]  76.83 49.4 90 bottom
TVS4  ESD5B5.0ST1G  [SOD523-2-28]  70.48 53.72 90 bottom
TVS5  ESD5B5.0ST1G  [SOD523-2-28]  68.96 53.72 90 bottom
TVS6  ESD5B5.0ST1G  [SOD523-2-28]  30.48 9.53 270 top
TVS7  ESD5B5.0ST1G  [SOD523-2-28]  27.94 9.53 270 top
TVS8  ESD5B5.0ST1G  [SOD523-2-28]  25.4 9.53 270 top
TVS9  ESD5B5.0ST1G  [SOD523-2-28]  22.86 9.53 270 top
TVS10  ESD5B5.0ST1G  [SOD523-2-28]  20.32 9.53 270 top
TVS11  ESD5B5.0ST1G  [SOD523-2-28]  16.51 9.53 270 top
TVS12  ESD5B5.0ST1G  [SOD523-2-28]  72.66 84.45 180 bottom
TVS13  ESD5B5.0ST1G  [SOD523-2-28]  66.55 133.99 90 top
TVS14  ESD5B5.0ST1G  [SOD523-2-28]  69.72 133.99 270 top
U1  K230-USIP  [BBGA390-065-1313-020]  28.57 80.01 270 top
U3  DIO7002AST5  [SOT23-5-36]  68.71 68.45 90 top
U4  TF-01A  [CARD-MICRO-SD-9-80]  73.42 88.27 90 top
U5  LP4-1Gb-X16-SDP  [BGA200-080065-1510-009]  22.23 51.44 0 top
U6  DIO7002AST5  [SOT23-5-36]  68.71 58.29 90 top
U7  LP4-1Gb-X16-SDP  [BGA200-080065-1510-009]  34.92 51.44 0 top
U9  TLV75801PDRVR  [DFN6-065-0202-008-N]  26.04 24.77 0 top
U16  HT6818SQER  [QFN20-050-0404-008-N]  58.42 122.56 0 top
U22  PRTR5V0U2X  [SOT143-4-48]  66.04 86.36 0 bottom
U23  PRTR5V0U2X  [SOT143-4-48]  66.04 82.55 0 bottom
U24  PRTR5V0U2X  [SOT143-4-48]  66.04 90.17 0 bottom
U25  SGM4574YUQN12G  [QFN12-040-018018-006]  67.2 117.59 270 top
U26  FT2232HQ  [QFN64-050-0909-010-N]  60.71 108.48 180 top
U29  MSM381ACT001  [MIC4-028019-010]  69.22 137.79 180 top
U30  KLM4G1FETE-B041  [BGA153-050-011010-008]  41.91 113.03 180 top
U31  PRTR5V0U2X  [SOT143-4-48]  68.58 62.74 180 top
U32  PRTR5V0U2X  [SOT143-4-48]  68.58 72.77 180 top
U33  PRTR5V0U2X  [SOT143-4-48]  68.58 76.83 180 top
U34  SGM4574YUQN12G  [QFN12-040-018018-006]  60.58 100.33 0 top
U35  RY1314  [QFN24-050-0404-010-N]  52.7 32.38 90 top
U36  SGM4574YUQN12G  [QFN12-040-018018-006]  53.21 108.97 270 top
U37  TLV75801PDRVR  [DFN6-065-0202-008-N]  61.34 91.19 0 top
U38  SY8003EDFC  [QFN8-050-0202-008-N]  60.45 76.83 0 top
U39  RT9013-33GB  [SOT23-5-57]  26.04 19.05 270 top
V-TS  TEST POINT SMD circle 35 mils  [TP28]  47.37 81.53 0 top
Y1  32.768KHZ  [X2-3215-008]  51.44 74.04 90 top
Y3  24MHz-3225  [X4-3225-007]  52.07 79.63 90 top
Y5  12MHz  [X4-2520-010]  67.94 100.2 180 top

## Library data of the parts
C1-C123 C127-C129 C139 C145 C149-C162 C199-C208 C216-C227 C238 C242 C244 C256-C266 C268 C269 C272-C354 C357-C362 C365-C383 C394-C404 = CAP NP
C247-C254 = CAP POL
D1 = MM5Z5V6ST1G
F1 = 3A-12V
FB1 FB4 FB5 FB7 FB8 FB19 FB26 FB27 FB29 FB31 FB32 FB34 FB38 = FB
GPIO1 GPIO25 V-TS = TEST_POINT_ SMD_circle_35mils
J1 J5 J8 = CON2X8
J2 J6 J11 J13 = type-c-smd
J3 = TH243-G60S-W0R01
J4 = 30PIN_CONNECT_2D54MM_FPC
J7 = PJ35367
J9 = Flash-EXT
J12 = CON10
J14 J16 J17 J22 = CON2
J15 = CON6
J18 J19 = 2P-SMD-1.25
J20 J21 = CON3
K1 = KH-6X6X8H-ZJ
K2 = TS-KG07U
K4 = SK12D07VG3
L4 L5 L7 L11 L12 = INDUCTOR
LED1 = LED
M1-M6 = M3
Q1 = YJL2301C
Q2 = 2N7002
Q5 = YJL3407AL
R1-R6 R8 R10 R12-R17 R22 R25-R30 R33 R34 R47 R50-R52 R55 R64 R77 R79 R81 R83 R85 R87 R89 R91-R128 R179-R184 R208 R221 R245 = RESISTOR: signal model: RESISTOR_R0402_0R_0R
R7 R9 R11 R18-R20 R23 R35 R40-R42 R44-R46 R48 R49 R56-R58 R61-R63 R66-R69 R72-R76 R78 R80 R82 R84 R86 R88 R90 R129-R134 R137 R141 R143 R144 R146 R147 R162 R188-R191 R193-R195 R197 R199-R207 R209 R223 R234-R243 R252 R262 R265 R272-R274 R277-R282 R284 R287-R290 R293 R301 R302 R304 R309-R312 = RESISTOR
R31 R39 R43 R177 R178 R266-R271 R275 R276 R283 R285 R286 R294 R296 R303 R305-R308 = Resistor
R53 R54 R59 R65 R198 = RESISTOR: signal model: RESISTOR_R0402_NC_NC
SW1 = SW_SMD_2P54
TP1-TP28 = T POINT S
TVS1-TVS14 = DIODE_TVS_BIDIR
U1 = K230 USIP 13M2
U3 U6 = DIO7002AST5
U4 = CONN_MICRO_SDCARD_9P
U5 U7 = LP4-1Gb-X16-SDP
U9 U37 = IC_LDO_TLV758P
U16 = HT6818SQER
U22-U24 U31-U33 = PRTR5V0U2X
U25 U34 U36 = SGM4574YUQN12G
U26 = FT2232HQ
U29 = MSM381ACT001
U30 = KLM4G1FETE-B041
U35 = RY1314
U38 = SY8003EDFC
U39 = RT9013-33GB
Y1 = CRYSTAL_2
Y3 Y5 = CRYSTAL_4

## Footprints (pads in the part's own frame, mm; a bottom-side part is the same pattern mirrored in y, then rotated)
AUDIO-PJ3536-7-197
  round 1.219 hole 1.219 unplated: (0,3.4) (0,-3.6)
  rect 2.286x1.27 smd: 1(-3.25,3) 2(-3.25,0.1) 3(-3.25,-2.8) 4(3.25,-3.1) 6(3.25,1.9) 7(3.25,-1) 8(-3.25,-5.1)
BBGA390-065-1313-020
  round 0.305 smd: A2(-5.525,6.175) A3(-4.875,6.175) A4(-4.225,6.175) A5(-3.575,6.175) A6(-2.925,6.175) A7(-2.275,6.175) A8(-1.625,6.175) A9(-0.975,6.175) A10(-0.325,6.175) A11(0.325,6.175) A12(0.975,6.175) A13(1.625,6.175) A14(2.275,6.175) A15(2.925,6.175) A16(3.575,6.175) A17(4.225,6.175) A18(4.875,6.175) A19(5.525,6.175) A20(6.175,6.175) B1(-6.175,5.525) B2(-5.525,5.525) B3(-4.875,5.525) B4(-4.225,5.525) B5(-3.575,5.525) B6(-2.925,5.525) B7(-2.275,5.525) B8(-1.625,5.525) B9(-0.975,5.525) B10(-0.325,5.525) B11(0.325,5.525) B12(0.975,5.525) B13(1.625,5.525) B14(2.275,5.525) B15(2.925,5.525) B16(3.575,5.525) B17(4.225,5.525) B18(4.875,5.525) B19(5.525,5.525) B20(6.175,5.525) C1(-6.175,4.875) C2(-5.525,4.875) C3(-4.875,4.875) C4(-4.225,4.875) C5(-3.575,4.875) C6(-2.925,4.875) C7(-2.275,4.875) C8(-1.625,4.875) C9(-0.975,4.875) C10(-0.325,4.875) C11(0.325,4.875) C12(0.975,4.875) C13(1.625,4.875) C14(2.275,4.875) C15(2.925,4.875) C16(3.575,4.875) C17(4.225,4.875) C18(4.875,4.875) C19(5.525,4.875) C20(6.175,4.875) D1(-6.175,4.225) D2(-5.525,4.225) D3(-4.875,4.225) D4(-4.225,4.225) D5(-3.575,4.225) D6(-2.925,4.225) D7(-2.275,4.225) D8(-1.625,4.225) D9(-0.975,4.225) D10(-0.325,4.225) D11(0.325,4.225) D12(0.975,4.225) D13(1.625,4.225) D14(2.275,4.225) D15(2.925,4.225) D16(3.575,4.225) D17(4.225,4.225) D18(4.875,4.225) D19(5.525,4.225) D20(6.175,4.225) E1(-6.175,3.575) E2(-5.525,3.575) E3(-4.875,3.575) E4(-4.225,3.575) E6(-2.925,3.575) E7(-2.275,3.575) E8(-1.625,3.575) E9(-0.975,3.575) E10(-0.325,3.575) E11(0.325,3.575) E12(0.975,3.575) E13(1.625,3.575) E14(2.275,3.575) E15(2.925,3.575) E16(3.575,3.575) E17(4.225,3.575) E18(4.875,3.575) E19(5.525,3.575) E20(6.175,3.575) F1(-6.175,2.925) F2(-5.525,2.925) F3(-4.875,2.925) F4(-4.225,2.925) F6(-2.925,2.925) F7(-2.275,2.925) F8(-1.625,2.925) F9(-0.975,2.925) F10(-0.325,2.925) F11(0.325,2.925) F12(0.975,2.925) F13(1.625,2.925) F14(2.275,2.925) F15(2.925,2.925) F16(3.575,2.925) F17(4.225,2.925) F18(4.875,2.925) F19(5.525,2.925) F20(6.175,2.925) G1(-6.175,2.275) G2(-5.525,2.275) G3(-4.875,2.275) G4(-4.225,2.275) G5(-3.575,2.275) G6(-2.925,2.275) G7(-2.275,2.275) G8(-1.625,2.275) G9(-0.975,2.275) G10(-0.325,2.275) G11(0.325,2.275) G12(0.975,2.275) G13(1.625,2.275) G14(2.275,2.275) G15(2.925,2.275) G16(3.575,2.275) G17(4.225,2.275) G18(4.875,2.275) G19(5.525,2.275) G20(6.175,2.275) H1(-6.175,1.625) H2(-5.525,1.625) H3(-4.875,1.625) H4(-4.225,1.625) H5(-3.575,1.625) H6(-2.925,1.625) H7(-2.275,1.625) H8(-1.625,1.625) H9(-0.975,1.625) H10(-0.325,1.625) H11(0.325,1.625) H12(0.975,1.625) H13(1.625,1.625) H14(2.275,1.625) H15(2.925,1.625) H16(3.575,1.625) H17(4.225,1.625) H18(4.875,1.625) H19(5.525,1.625) H20(6.175,1.625) J1(-6.175,0.975) J2(-5.525,0.975) J3(-4.875,0.975) J4(-4.225,0.975) J5(-3.575,0.975) J6(-2.925,0.975) J7(-2.275,0.975) J8(-1.625,0.975) J9(-0.975,0.975) J10(-0.325,0.975) J11(0.325,0.975) J12(0.975,0.975) J13(1.625,0.975) J14(2.275,0.975) J15(2.925,0.975) J16(3.575,0.975) J17(4.225,0.975) J18(4.875,0.975) J19(5.525,0.975) J20(6.175,0.975) K1(-6.175,0.325) K2(-5.525,0.325) K3(-4.875,0.325) K4(-4.225,0.325) K5(-3.575,0.325) K6(-2.925,0.325) K7(-2.275,0.325) K8(-1.625,0.325) K9(-0.975,0.325) K10(-0.325,0.325) K11(0.325,0.325) K12(0.975,0.325) K13(1.625,0.325) K14(2.275,0.325) K15(2.925,0.325) K16(3.575,0.325) K17(4.225,0.325) K18(4.875,0.325) K19(5.525,0.325) K20(6.175,0.325) L1(-6.175,-0.325) L2(-5.525,-0.325) L3(-4.875,-0.325) L4(-4.225,-0.325) L5(-3.575,-0.325) L6(-2.925,-0.325) L7(-2.275,-0.325) L8(-1.625,-0.325) L9(-0.975,-0.325) L10(-0.325,-0.325) L11(0.325,-0.325) L12(0.975,-0.325) L13(1.625,-0.325) L14(2.275,-0.325) L15(2.925,-0.325) L16(3.575,-0.325) L17(4.225,-0.325) L18(4.875,-0.325) L19(5.525,-0.325) L20(6.175,-0.325) M1(-6.175,-0.975) M2(-5.525,-0.975) M3(-4.875,-0.975) M4(-4.225,-0.975) M5(-3.575,-0.975) M6(-2.925,-0.975) M7(-2.275,-0.975) M8(-1.625,-0.975) M9(-0.975,-0.975) M10(-0.325,-0.975) M11(0.325,-0.975) M12(0.975,-0.975) M13(1.625,-0.975) M14(2.275,-0.975) M15(2.925,-0.975) M16(3.575,-0.975) M17(4.225,-0.975) M18(4.875,-0.975) M19(5.525,-0.975) M20(6.175,-0.975) N1(-6.175,-1.625) N2(-5.525,-1.625) N3(-4.875,-1.625) N4(-4.225,-1.625) N5(-3.575,-1.625) N6(-2.925,-1.625) N7(-2.275,-1.625) N8(-1.625,-1.625) N9(-0.975,-1.625) N10(-0.325,-1.625) N11(0.325,-1.625) N12(0.975,-1.625) N13(1.625,-1.625) N14(2.275,-1.625) N15(2.925,-1.625) N16(3.575,-1.625) N17(4.225,-1.625) N18(4.875,-1.625) N19(5.525,-1.625) N20(6.175,-1.625) P1(-6.175,-2.275) P2(-5.525,-2.275) P3(-4.875,-2.275) P4(-4.225,-2.275) P5(-3.575,-2.275) P6(-2.925,-2.275) P7(-2.275,-2.275) P8(-1.625,-2.275) P9(-0.975,-2.275) P10(-0.325,-2.275) P11(0.325,-2.275) P12(0.975,-2.275) P13(1.625,-2.275) P14(2.275,-2.275) P15(2.925,-2.275) P16(3.575,-2.275) P17(4.225,-2.275) P18(4.875,-2.275) P19(5.525,-2.275) P20(6.175,-2.275) R1(-6.175,-2.925) R2(-5.525,-2.925) R3(-4.875,-2.925) R6(-2.925,-2.925) R7(-2.275,-2.925) R8(-1.625,-2.925) R9(-0.975,-2.925) R10(-0.325,-2.925) R11(0.325,-2.925) R12(0.975,-2.925) R13(1.625,-2.925) R14(2.275,-2.925) R15(2.925,-2.925) R16(3.575,-2.925) R17(4.225,-2.925) R18(4.875,-2.925) R19(5.525,-2.925) R20(6.175,-2.925) T1(-6.175,-3.575) T2(-5.525,-3.575) T3(-4.875,-3.575) T7(-2.275,-3.575) T8(-1.625,-3.575) T9(-0.975,-3.575) T10(-0.325,-3.575) T11(0.325,-3.575) T12(0.975,-3.575) T13(1.625,-3.575) T14(2.275,-3.575) T15(2.925,-3.575) T16(3.575,-3.575) T17(4.225,-3.575) T18(4.875,-3.575) T19(5.525,-3.575) T20(6.175,-3.575) U1(-6.175,-4.225) U2(-5.525,-4.225) U3(-4.875,-4.225) U6(-2.925,-4.225) U7(-2.275,-4.225) U8(-1.625,-4.225) U9(-0.975,-4.225) U10(-0.325,-4.225) U11(0.325,-4.225) U12(0.975,-4.225) U13(1.625,-4.225) U14(2.275,-4.225) U15(2.925,-4.225) U16(3.575,-4.225) U17(4.225,-4.225) U18(4.875,-4.225) U19(5.525,-4.225) U20(6.175,-4.225) V1(-6.175,-4.875) V2(-5.525,-4.875) V3(-4.875,-4.875) V4(-4.225,-4.875) V5(-3.575,-4.875) V6(-2.925,-4.875) V7(-2.275,-4.875) V8(-1.625,-4.875) V9(-0.975,-4.875) V10(-0.325,-4.875) V11(0.325,-4.875) V12(0.975,-4.875) V13(1.625,-4.875) V14(2.275,-4.875) V15(2.925,-4.875) V16(3.575,-4.875) V17(4.225,-4.875) V18(4.875,-4.875) V19(5.525,-4.875) V20(6.175,-4.875) W1(-6.175,-5.525) W2(-5.525,-5.525) W3(-4.875,-5.525) W4(-4.225,-5.525) W5(-3.575,-5.525) W6(-2.925,-5.525) W7(-2.275,-5.525) W8(-1.625,-5.525) W9(-0.975,-5.525) W10(-0.325,-5.525) W11(0.325,-5.525) W12(0.975,-5.525) W13(1.625,-5.525) W14(2.275,-5.525) W15(2.925,-5.525) W16(3.575,-5.525) W17(4.225,-5.525) W18(4.875,-5.525) W19(5.525,-5.525) W20(6.175,-5.525) Y1(-6.175,-6.175) Y2(-5.525,-6.175) Y3(-4.875,-6.175) Y4(-4.225,-6.175) Y5(-3.575,-6.175) Y6(-2.925,-6.175) Y7(-2.275,-6.175) Y8(-1.625,-6.175) Y9(-0.975,-6.175) Y10(-0.325,-6.175) Y11(0.325,-6.175) Y12(0.975,-6.175) Y13(1.625,-6.175) Y14(2.275,-6.175) Y15(2.925,-6.175) Y16(3.575,-6.175) Y17(4.225,-6.175) Y18(4.875,-6.175) Y19(5.525,-6.175) Y20(6.175,-6.175)
BGA153-050-011010-008
  round 0.254 smd: A1(-3.25,3.25) A2(-2.75,3.25) A3(-2.25,3.25) A4(-1.75,3.25) A5(-1.25,3.25) A6(-0.75,3.25) A7(-0.25,3.25) A8(0.25,3.25) A9(0.75,3.25) A10(1.25,3.25) A11(1.75,3.25) A12(2.25,3.25) A13(2.75,3.25) A14(3.25,3.25) B1(-3.25,2.75) B2(-2.75,2.75) B3(-2.25,2.75) B4(-1.75,2.75) B5(-1.25,2.75) B6(-0.75,2.75) B7(-0.25,2.75) B8(0.25,2.75) B9(0.75,2.75) B10(1.25,2.75) B11(1.75,2.75) B12(2.25,2.75) B13(2.75,2.75) B14(3.25,2.75) C1(-3.25,2.25) C2(-2.75,2.25) C3(-2.25,2.25) C4(-1.75,2.25) C5(-1.25,2.25) C6(-0.75,2.25) C7(-0.25,2.25) C8(0.25,2.25) C9(0.75,2.25) C10(1.25,2.25) C11(1.75,2.25) C12(2.25,2.25) C13(2.75,2.25) C14(3.25,2.25) D1(-3.25,1.75) D2(-2.75,1.75) D3(-2.25,1.75) D4(-1.75,1.75) D12(2.25,1.75) D13(2.75,1.75) D14(3.25,1.75) E1(-3.25,1.25) E2(-2.75,1.25) E3(-2.25,1.25) E5(-1.25,1.25) E6(-0.75,1.25) E7(-0.25,1.25) E8(0.25,1.25) E9(0.75,1.25) E10(1.25,1.25) E12(2.25,1.25) E13(2.75,1.25) E14(3.25,1.25) F1(-3.25,0.75) F2(-2.75,0.75) F3(-2.25,0.75) F5(-1.25,0.75) F10(1.25,0.75) F12(2.25,0.75) F13(2.75,0.75) F14(3.25,0.75) G1(-3.25,0.25) G2(-2.75,0.25) G3(-2.25,0.25) G5(-1.25,0.25) G10(1.25,0.25) G12(2.25,0.25) G13(2.75,0.25) G14(3.25,0.25) H1(-3.25,-0.25) H2(-2.75,-0.25) H3(-2.25,-0.25) H5(-1.25,-0.25) H10(1.25,-0.25) H12(2.25,-0.25) H13(2.75,-0.25) H14(3.25,-0.25) J1(-3.25,-0.75) J2(-2.75,-0.75) J3(-2.25,-0.75) J5(-1.25,-0.75) J10(1.25,-0.75) J12(2.25,-0.75) J13(2.75,-0.75) J14(3.25,-0.75) K1(-3.25,-1.25) K2(-2.75,-1.25) K3(-2.25,-1.25) K5(-1.25,-1.25) K6(-0.75,-1.25) K7(-0.25,-1.25) K8(0.25,-1.25) K9(0.75,-1.25) K10(1.25,-1.25) K12(2.25,-1.25) K13(2.75,-1.25) K14(3.25,-1.25) L1(-3.25,-1.75) L2(-2.75,-1.75) L3(-2.25,-1.75) L12(2.25,-1.75) L13(2.75,-1.75) L14(3.25,-1.75) M1(-3.25,-2.25) M2(-2.75,-2.25) M3(-2.25,-2.25) M4(-1.75,-2.25) M5(-1.25,-2.25) M6(-0.75,-2.25) M7(-0.25,-2.25) M8(0.25,-2.25) M9(0.75,-2.25) M10(1.25,-2.25) M11(1.75,-2.25) M12(2.25,-2.25) M13(2.75,-2.25) M14(3.25,-2.25) N1(-3.25,-2.75) N2(-2.75,-2.75) N3(-2.25,-2.75) N4(-1.75,-2.75) N5(-1.25,-2.75) N6(-0.75,-2.75) N7(-0.25,-2.75) N8(0.25,-2.75) N9(0.75,-2.75) N10(1.25,-2.75) N11(1.75,-2.75) N12(2.25,-2.75) N13(2.75,-2.75) N14(3.25,-2.75) P1(-3.25,-3.25) P2(-2.75,-3.25) P3(-2.25,-3.25) P4(-1.75,-3.25) P5(-1.25,-3.25) P6(-0.75,-3.25) P7(-0.25,-3.25) P8(0.25,-3.25) P9(0.75,-3.25) P10(1.25,-3.25) P11(1.75,-3.25) P12(2.25,-3.25) P13(2.75,-3.25) P14(3.25,-3.25)
BGA200-080065-1510-009
  round 0.279 smd: A1(-4.401,6.825) A2(-3.6,6.825) A3(-2.8,6.825) A4(-2,6.825) A5(-1.2,6.825) A8(1.2,6.825) A9(2,6.825) A10(2.8,6.825) A11(3.6,6.825) A12(4.401,6.825) AA1(-4.401,-6.175) AA2(-3.6,-6.175) AA3(-2.8,-6.175) AA4(-2,-6.175) AA5(-1.2,-6.175) AA8(1.2,-6.175) AA9(2,-6.175) AA10(2.8,-6.175) AA11(3.6,-6.175) AA12(4.401,-6.175) AB1(-4.401,-6.825) AB2(-3.6,-6.825) AB3(-2.8,-6.825) AB4(-2,-6.825) AB5(-1.2,-6.825) AB8(1.2,-6.825) AB9(2,-6.825) AB10(2.8,-6.825) AB11(3.6,-6.825) AB12(4.401,-6.825) B1(-4.401,6.175) B2(-3.6,6.175) B3(-2.8,6.175) B4(-2,6.175) B5(-1.2,6.175) B8(1.2,6.175) B9(2,6.175) B10(2.8,6.175) B11(3.6,6.175) B12(4.401,6.175) C1(-4.401,5.525) C2(-3.6,5.525) C3(-2.8,5.525) C4(-2,5.525) C5(-1.2,5.525) C8(1.2,5.525) C9(2,5.525) C10(2.8,5.525) C11(3.6,5.525) C12(4.401,5.525) D1(-4.401,4.875) D2(-3.6,4.875) D3(-2.8,4.875) D4(-2,4.875) D5(-1.2,4.875) D8(1.2,4.875) D9(2,4.875) D10(2.8,4.875) D11(3.6,4.875) D12(4.401,4.875) E1(-4.401,4.225) E2(-3.6,4.225) E3(-2.8,4.225) E4(-2,4.225) E5(-1.2,4.225) E8(1.2,4.225) E9(2,4.225) E10(2.8,4.225) E11(3.6,4.225) E12(4.401,4.225) F1(-4.401,3.575) F2(-3.6,3.575) F3(-2.8,3.575) F4(-2,3.575) F5(-1.2,3.575) F8(1.2,3.575) F9(2,3.575) F10(2.8,3.575) F11(3.6,3.575) F12(4.401,3.575) G1(-4.401,2.925) G2(-3.6,2.925) G3(-2.8,2.925) G4(-2,2.925) G5(-1.2,2.925) G8(1.2,2.925) G9(2,2.925) G10(2.8,2.925) G11(3.6,2.925) G12(4.401,2.925) H1(-4.401,2.275) H2(-3.6,2.275) H3(-2.8,2.275) H4(-2,2.275) H5(-1.2,2.275) H8(1.2,2.275) H9(2,2.275) H10(2.8,2.275) H11(3.6,2.275) H12(4.401,2.275) J1(-4.401,1.625) J2(-3.6,1.625) J3(-2.8,1.625) J4(-2,1.625) J5(-1.2,1.625) J8(1.2,1.625) J9(2,1.625) J10(2.8,1.625) J11(3.6,1.625) J12(4.401,1.625) K1(-4.401,0.975) K2(-3.6,0.975) K3(-2.8,0.975) K4(-2,0.975) K5(-1.2,0.975) K8(1.2,0.975) K9(2,0.975) K10(2.8,0.975) K11(3.6,0.975) K12(4.401,0.975) N1(-4.401,-0.975) N2(-3.6,-0.975) N3(-2.8,-0.975) N4(-2,-0.975) N5(-1.2,-0.975) N8(1.2,-0.975) N9(2,-0.975) N10(2.8,-0.975) N11(3.6,-0.975) N12(4.401,-0.975) P1(-4.401,-1.625) P2(-3.6,-1.625) P3(-2.8,-1.625) P4(-2,-1.625) P5(-1.2,-1.625) P8(1.2,-1.625) P9(2,-1.625) P10(2.8,-1.625) P11(3.6,-1.625) P12(4.401,-1.625) R1(-4.401,-2.275) R2(-3.6,-2.275) R3(-2.8,-2.275) R4(-2,-2.275) R5(-1.2,-2.275) R8(1.2,-2.275) R9(2,-2.275) R10(2.8,-2.275) R11(3.6,-2.275) R12(4.401,-2.275) T1(-4.401,-2.925) T2(-3.6,-2.925) T3(-2.8,-2.925) T4(-2,-2.925) T5(-1.2,-2.925) T8(1.2,-2.925) T9(2,-2.925) T10(2.8,-2.925) T11(3.6,-2.925) T12(4.401,-2.925) U1(-4.401,-3.575) U2(-3.6,-3.575) U3(-2.8,-3.575) U4(-2,-3.575) U5(-1.2,-3.575) U8(1.2,-3.575) U9(2,-3.575) U10(2.8,-3.575) U11(3.6,-3.575) U12(4.401,-3.575) V1(-4.401,-4.225) V2(-3.6,-4.225) V3(-2.8,-4.225) V4(-2,-4.225) V5(-1.2,-4.225) V8(1.2,-4.225) V9(2,-4.225) V10(2.8,-4.225) V11(3.6,-4.225) V12(4.401,-4.225) W1(-4.401,-4.875) W2(-3.6,-4.875) W3(-2.8,-4.875) W4(-2,-4.875) W5(-1.2,-4.875) W8(1.2,-4.875) W9(2,-4.875) W10(2.8,-4.875) W11(3.6,-4.875) W12(4.401,-4.875) Y1(-4.401,-5.525) Y2(-3.6,-5.525) Y3(-2.8,-5.525) Y4(-2,-5.525) Y5(-1.2,-5.525) Y8(1.2,-5.525) Y9(2,-5.525) Y10(2.8,-5.525) Y11(3.6,-5.525) Y12(4.401,-5.525)
BTB2X30-050-F-SMD
  round 0.61 hole 0.61 unplated: (-8.3,1.5) (8.3,1.5)
  rect 0.305x1.651 smd: 1(-7.252,-1.825) 2(-7.252,1.825) 3(-6.752,-1.825) 4(-6.752,1.825) 5(-6.252,-1.825) 6(-6.252,1.825) 7(-5.752,-1.825) 8(-5.752,1.825) 9(-5.251,-1.825) 10(-5.251,1.825) 11(-4.751,-1.825) 12(-4.751,1.825) 13(-4.251,-1.825) 14(-4.251,1.825) 15(-3.751,-1.825) 16(-3.751,1.825) 17(-3.251,-1.825) 18(-3.251,1.825) 19(-2.751,-1.825) 20(-2.751,1.825) 21(-2.251,-1.825) 22(-2.251,1.825) 23(-1.751,-1.825) 24(-1.751,1.825) 25(-1.25,-1.825) 26(-1.25,1.825) 27(-0.75,-1.825) 28(-0.75,1.825) 29(-0.25,-1.825) 30(-0.25,1.825) 31(0.25,-1.825) 32(0.25,1.825) 33(0.75,-1.825) 34(0.75,1.825) 35(1.25,-1.825) 36(1.25,1.825) 37(1.75,-1.825) 38(1.75,1.825) 39(2.25,-1.825) 40(2.25,1.825) 41(2.751,-1.825) 42(2.751,1.825) 43(3.251,-1.825) 44(3.251,1.825) 45(3.751,-1.825) 46(3.751,1.825) 47(4.251,-1.825) 48(4.251,1.825) 49(4.751,-1.825) 50(4.751,1.825) 51(5.251,-1.825) 52(5.251,1.825) 53(5.751,-1.825) 54(5.751,1.825) 55(6.251,-1.825) 56(6.251,1.825) 57(6.752,-1.825) 58(6.752,1.825) 59(7.252,-1.825) 60(7.252,1.825)
C0402
  rect 0.635x0.508 smd: 1(-0.508,0) 2(0.508,0)
C0603
  rect 0.889x0.813 smd: 1(-0.762,0) 2(0.762,0)
C0805
  rect 1.016x1.397 smd: 1(-0.889,0) 2(0.889,0)
C1010_8383_6666
  rect 1.27x4.928 smd: 1(0,-3.352) 2(0,3.352)
C1206
  rect 1.397x1.651 smd: 1(-1.397,0) 2(1.397,0)
CARD-MICRO-SD-9-80
  round 1.016 hole 1.016 unplated: (-4.928,-2.65) (3.072,-2.65)
  rect 0.711x1.6 smd: 1(2.221,7.926) 2(1.121,7.926) 3(0.022,7.926) 4(-1.078,7.926) 5(-2.179,7.926) 6(-3.278,7.926) 7(-4.378,7.926) 8(-5.479,7.926) 9(-6.579,7.926)
  rect 1.016x2.032 smd: 10(-7.931,7.35) 12(7.874,-2.25) 13(-7.931,-2.25)
  rect 1.397x1.6 smd: 11(6.821,7.35)
CON2-075053-036
  rect 1.778x2.54 smd: (-3.075,-0.167) (3.075,-0.167)
  rect 0.711x1.778 smd: 1(-0.625,-2.667) 2(0.625,-2.667)
DFN6-065-0202-008-N
  rect 0.457x0.381 smd: 1(-0.975,0.65) 2(-0.975,0) 3(-0.975,-0.65) 4(0.975,-0.65) 5(0.975,0) 6(0.975,0.65)
  rect 0.991x1.6 smd: 7(0,0)
